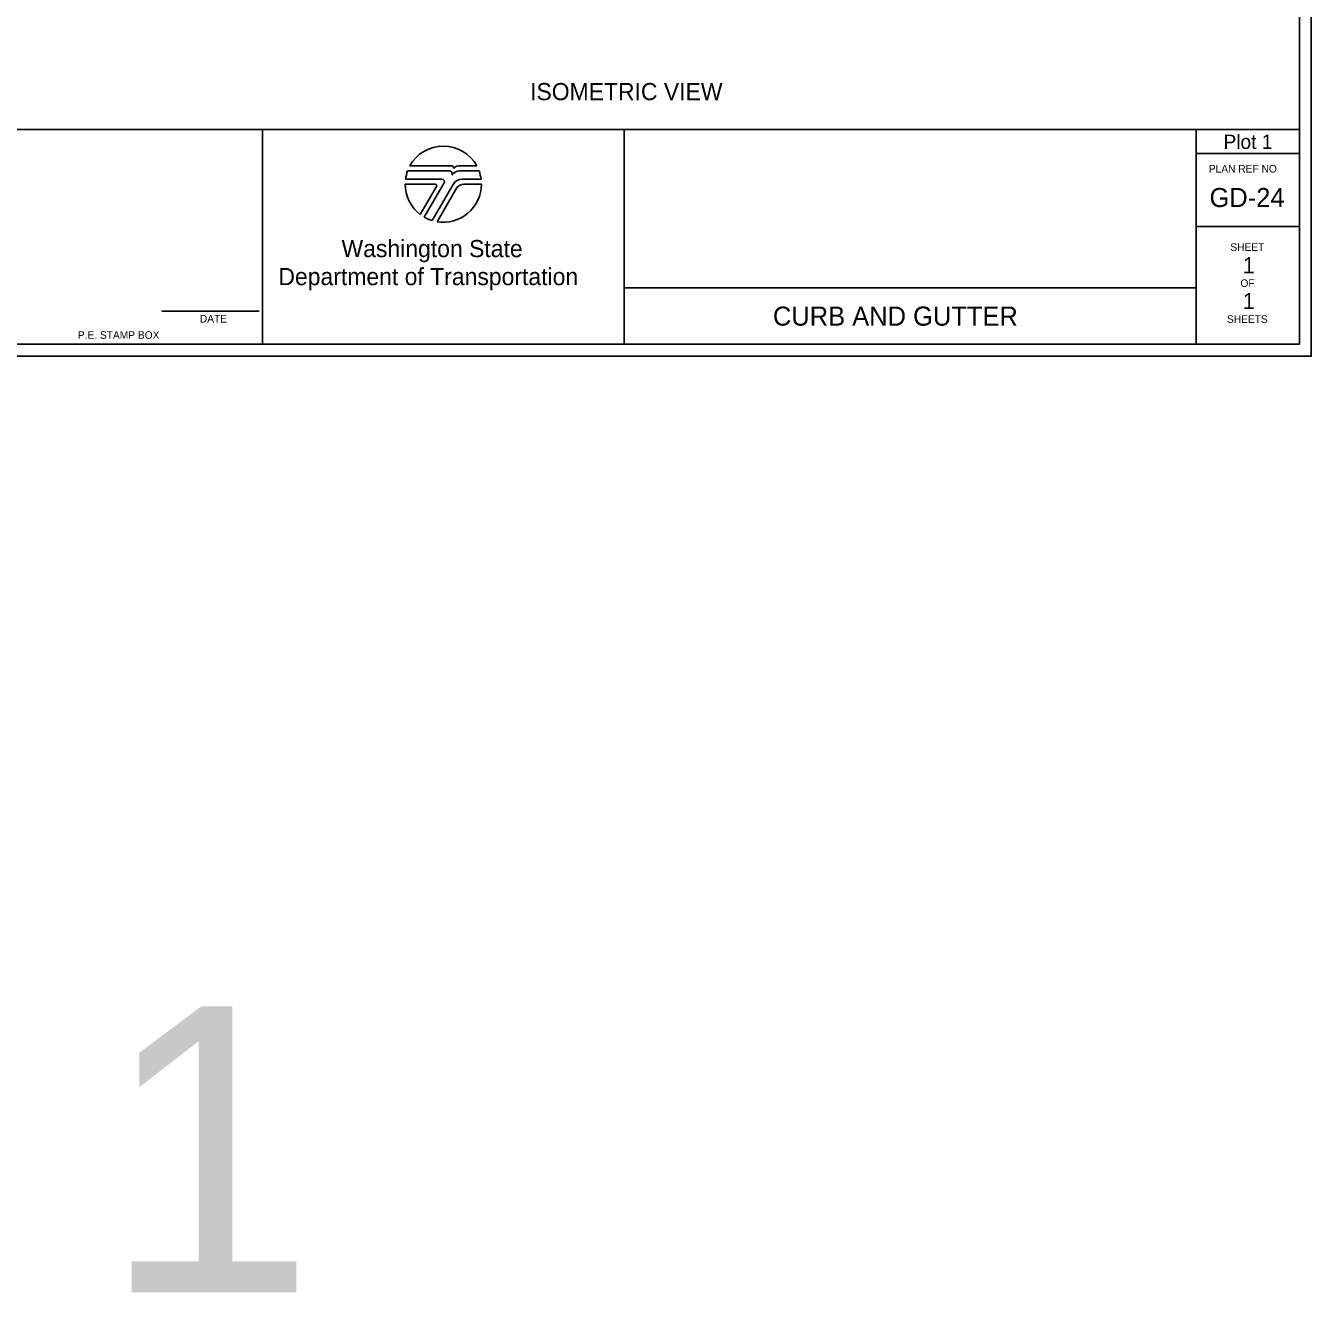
# Model space of a CAD drawing. Extents: x 99988 to 100172, y 99995 to 100047.
# Drawn here: x 100009.07 to 100015.81, y 99995.01 to 100001.67 of the extents above; entities that cross this region are included whole.
import ezdxf

# ---------------------------------------------------------------- set-up
doc = ezdxf.new("R2010")
doc.units = 0
for name, color, linetype in [('Level 20', 7, 'Continuous'), ('SH_GI_PlotLimits', 7, 'Continuous'), ('SH_GI_SheetBorder', 7, 'Continuous'), ('SH_GI_SheetLocationText', 7, 'Continuous'), ('SH_GI_SheetTextInCells', 7, 'Continuous'), ('SH_GI_TitleBlockText', 7, 'Continuous'), ('SH_GI_WSDOTLogo', 7, 'Continuous')]:
    doc.layers.add(name, color=color, linetype=linetype)

msp = doc.modelspace()

# ---------------------------------------------------------------- linework, layer by layer
at = {"layer": 'SH_GI_PlotLimits'}
msp.add_lwpolyline([(99999.3125, 99999.9375), (100015.8125, 99999.9375), (100015.8125, 100010.4375), (99999.3125, 100010.4375)], close=True, dxfattribs=at)
at = {"layer": 'SH_GI_SheetBorder'}
for p, q in [((100015.75, 100010.375), (100015.75, 100000)), ((100000, 100001.1259), (100015.75, 100001.1259)), ((100010.3089, 100001.1259), (100010.3089, 100000)), ((100012.2055, 100001.1259), (100012.2055, 100000)), ((100015.2079, 100001.1259), (100015.2079, 100000)), ((100015.2079, 100001.0008), (100015.75, 100001.0008)), ((100015.2079, 100000.6176), (100015.75, 100000.6176)), ((100012.2055, 100000.2955), (100015.2079, 100000.2955)), ((100009.7797, 100000.1733), (100010.2914, 100000.1733)), ((100000, 100000), (100015.75, 100000))]:
    msp.add_line(p, q, dxfattribs=at)
at = {"layer": 'SH_GI_WSDOTLogo'}
for p, q in [((100011.303, 100000.9354), (100011.0815, 100000.9354)), ((100011.433, 100000.9354), (100011.3351, 100000.9354)), ((100011.059, 100000.8661), (100011.2496, 100000.8661)), ((100011.2894, 100000.9094), (100011.0697, 100000.9094)), ((100011.343, 100000.9094), (100011.3429, 100000.9094)), ((100011.4448, 100000.9094), (100011.343, 100000.9094)), ((100011.3558, 100000.8661), (100011.4555, 100000.8661)), ((100011.0572, 100000.84), (100011.2148, 100000.84)), ((100011.222, 100000.8277), (100011.1364, 100000.6807)), ((100011.261, 100000.8464), (100011.1567, 100000.6672)), ((100011.1989, 100000.6487), (100011.3089, 100000.839)), ((100011.2244, 100000.6428), (100011.3242, 100000.8156)), ((100011.3655, 100000.8394), (100011.4572, 100000.8394))]:
    msp.add_line(p, q, dxfattribs=at)
for centre, radius, start, end in [((100011.2572, 100000.84), 0.2, 28.47865, 151.53204), ((100011.303, 100000.9263), 0.00903, 329.87418, 90.00328), ((100011.3352, 100000.9066), 0.0287, 90.00721, 148.16763), ((100011.2572, 100000.84), 0.2, 159.69598, 172.50569), ((100011.2497, 100000.853), 0.0131, 329.76834, 90), ((100011.2894, 100000.8946), 0.0148, 327.8418, 89.99855), ((100011.3429, 100000.861), 0.0484, 89.99529, 147.82376), ((100011.3558, 100000.8119), 0.0542, 90, 149.99738), ((100011.2572, 100000.84), 0.2, 7.49431, 20.29406), ((100011.2572, 100000.84), 0.2, 179.99864, 232.84327), ((100011.2149, 100000.8318), 0.0082, 329.74356, 90), ((100011.2572, 100000.84), 0.2, 260.54554, 359.80857), ((100011.3654, 100000.7918), 0.0476, 90, 150.05432), ((100011.2572, 100000.84), 0.2, 239.79292, 253.0448)]:
    msp.add_arc(centre, radius, start, end, dxfattribs=at)

# ---------------------------------------------------------------- texts
at = {"layer": 'Level 20'}
msp.add_text('ISOMETRIC VIEW', height=0.09, dxfattribs=at).set_placement((100011.7126, 100001.2806))
at = {"layer": 'SH_GI_SheetBorder'}
msp.add_text('PLAN REF NO', height=0.040032, dxfattribs=at).set_placement((100015.2747, 100000.9008))
at = {"layer": 'SH_GI_SheetLocationText'}
for height, p in [(0.075, (100015.3518, 100001.025)), (1.5, (100005.4547, 99995.0267))]:
    msp.add_text('Plot 1', height=height, dxfattribs=at).set_placement(p)
at = {"layer": 'SH_GI_SheetTextInCells'}
for s, height, p in [('Washington State', 0.090072, (100010.7229, 100000.4571)), ('SHEET', 0.04003, (100015.3877, 100000.4896)), ('Department of Transportation', 0.090072, (100010.3916, 100000.3101)), ('OF', 0.04003, (100015.4406, 100000.3008)), ('DATE', 0.04003, (100009.9794, 100000.1141)), ('SHEETS', 0.04003, (100015.3698, 100000.112)), ('P.E. STAMP BOX', 0.040032, (100009.339, 100000.0286))]:
    msp.add_text(s, height=height, dxfattribs=at).set_placement(p)
at = {"layer": 'SH_GI_TitleBlockText'}
for s, height, p in [('GD-24', 0.1, (100015.2785, 100000.72)), ('1', 0.085, (100015.453, 100000.3723)), ('1', 0.085, (100015.453, 100000.1843)), ('CURB AND GUTTER', 0.1, (100012.9871, 100000.0977))]:
    msp.add_text(s, height=height, dxfattribs=at).set_placement(p)

doc.saveas('drawing.dxf')
